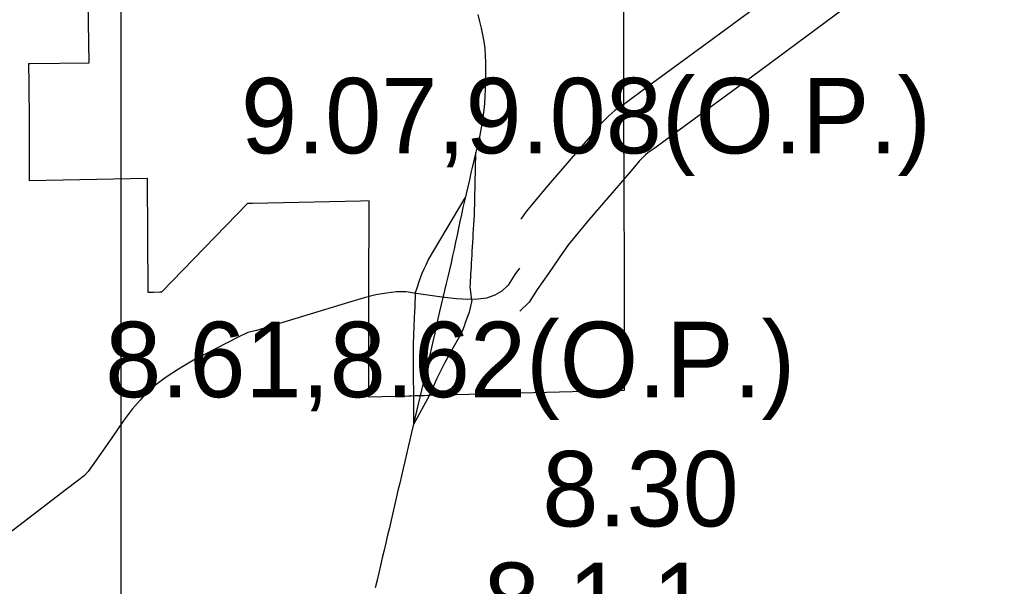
# Model space of a CAD drawing. Extents: x 1127717 to 1741049, y 2026793 to 2244711.
# Drawn here: x 1240828 to 1243581, y 2140586 to 2142172 of the extents above; entities that cross this region are included whole.
import ezdxf

# ---------------------------------------------------------------- set-up
doc = ezdxf.new("R2010")
doc.units = 0
for name, color, linetype in [('10', 7, 'Continuous'), ('30', 7, 'Continuous'), ('58', 7, 'Continuous'), ('6', 7, 'Continuous')]:
    doc.layers.add(name, color=color, linetype=linetype)

msp = doc.modelspace()

# ---------------------------------------------------------------- linework, layer by layer
at = {"layer": '10'}
for points in [[(1243898.9, 2143085.3), (1243769, 2142912), (1243734.4, 2142862.7), (1243709.9, 2142830.5), (1243698.6, 2142819.4), (1243674.7, 2142797.3), (1243491.4, 2142660.2), (1243211.8, 2142447.8), (1242963, 2142262.3), (1242790.6, 2142134.3), (1242584.6, 2141983.8), (1242522, 2141937.1), (1242493.2, 2141917.6), (1242476.6, 2141902.6), (1242450.7, 2141877.1), (1242424.4, 2141844.8), (1242306.6, 2141708.8), (1242245, 2141634.7), (1242230.2, 2141613.9)], [(1244018.9, 2142995.3), (1243890.4, 2142823.9), (1243855.5, 2142774.2), (1243822.8, 2142731.1), (1243802.2, 2142710.9), (1243771, 2142681.9), (1243581.7, 2142540.4), (1243302, 2142328), (1243052.6, 2142142), (1242879.6, 2142013.5), (1242673.7, 2141863.1), (1242608.9, 2141814.8), (1242585.9, 2141799.2), (1242579.4, 2141793.3), (1242561.8, 2141776), (1242539.3, 2141748.4), (1242421, 2141611.8), (1242363.9, 2141543.1), (1242339.2, 2141508.4), (1242308.1, 2141461.2), (1242275.8, 2141417), (1242253.4, 2141381.2), (1242227.4, 2141356.2)], [(1242109.8, 2142186), (1242114.7, 2142167.1), (1242119.1, 2142148.3), (1242123.1, 2142129.3), (1242126.5, 2142110.4), (1242129.4, 2142091.4), (1242131, 2142069), (1242131.7, 2142053.5), (1242131.4, 2142033.7)], [(1242131.4, 2142033.7), (1242131.6, 2142014.8), (1242131.3, 2141995.8), (1242130.7, 2141976.7), (1242129.8, 2141957.5), (1242128.4, 2141938), (1242126.5, 2141918.4), (1242124.1, 2141898.7), (1242121.2, 2141879), (1242117.8, 2141859.2), (1242113.9, 2141839.6), (1242109.6, 2141820.1), (1242104.9, 2141800.7), (1242100.1, 2141781.4), (1242095.4, 2141762.1), (1242090.9, 2141742.9), (1242086.5, 2141723.5), (1242082, 2141704.1), (1242077.4, 2141684.7), (1242072.8, 2141665.3), (1242068.3, 2141645.9), (1242064, 2141626.6), (1242059.9, 2141607.3), (1242055.9, 2141588), (1242052, 2141568.5), (1242048, 2141549.1)], [(1242093.7, 2141385.8), (1242089.2, 2141417.3), (1242089.1, 2141424.9), (1242089.5, 2141433), (1242089.9, 2141441.5), (1242090.4, 2141450.6), (1242090.9, 2141460), (1242091.4, 2141469.9), (1242092, 2141480.1), (1242092.7, 2141490.7), (1242093.3, 2141501.5), (1242094, 2141512.7), (1242094.7, 2141524.2), (1242095.4, 2141536), (1242096, 2141548), (1242096.7, 2141560.3), (1242097.5, 2141572.8), (1242098.3, 2141585.6), (1242099.2, 2141598.7), (1242100.9, 2141625.6), (1242104.8, 2141800.4)], [(1241959.6, 2141474.2), (1241965.4, 2141486.2), (1241971.6, 2141498.5), (1242074.8, 2141673.6)], [(1242048, 2141549.1), (1242043.8, 2141529.7), (1242039.6, 2141510.5), (1242035.2, 2141491.2), (1242030.8, 2141472), (1242026.3, 2141452.6), (1242021.7, 2141433.2), (1242017.1, 2141413.8), (1242012.5, 2141394.2), (1242007.8, 2141374.6), (1242003.3, 2141354.8), (1241998.7, 2141334.9), (1241994.1, 2141314.9), (1241989.5, 2141294.8), (1241984.8, 2141274.6), (1241980.2, 2141254.3), (1241975.5, 2141234), (1241970.8, 2141213.8), (1241966.2, 2141193.8), (1241961.7, 2141174), (1241957.1, 2141154.4), (1241952.5, 2141134.9), (1241947.9, 2141115.3), (1241943.2, 2141095.7), (1241938.6, 2141076), (1241934, 2141056.2), (1241929.4, 2141036.4), (1241924.9, 2141016.4), (1241920.3, 2140996.3), (1241915.6, 2140976.1), (1241910.7, 2140955.9), (1241905.9, 2140935.7), (1241901.1, 2140915.4), (1241896.3, 2140894.9), (1241891.5, 2140874.4), (1241886.7, 2140853.8), (1241881.9, 2140833.1), (1241877.1, 2140812.4), (1241872.3, 2140791.6), (1241867.5, 2140770.7), (1241862.6, 2140749.7), (1241857.7, 2140728.8), (1241852.8, 2140707.7), (1241847.9, 2140686.7), (1241842.9, 2140665.7), (1241838, 2140644.6), (1241833.1, 2140623.6), (1241828.2, 2140602.7), (1241823.3, 2140581.7)], [(1242226.6, 2141476.8), (1242213.7, 2141459.1), (1242194.8, 2141428.8), (1242177.4, 2141412.1), (1242157.8, 2141400.4), (1242134.6, 2141392.5), (1242110.8, 2141389.6), (1242081.8, 2141389.1), (1242050.8, 2141390.5), (1242009.2, 2141395.5), (1241937.9, 2141405.4), (1241909.3, 2141410.4), (1241882.8, 2141410), (1241855, 2141406.4), (1241825.2, 2141401.8), (1241792, 2141393.6), (1241748, 2141380.5), (1241490.6, 2141302.3), (1241466.4, 2141295.9), (1241439.4, 2141282.9), (1241314.3, 2141219.1), (1241272.7, 2141194), (1241235.2, 2141169.1), (1241202.1, 2141144.3), (1241183.2, 2141128.1), (1241165, 2141106.8), (1241142.9, 2141081.4), (1241118.1, 2141047.9), (1241085.8, 2141001.6), (1241030.7, 2140922.8), (1241019.7, 2140907.3), (1241008.7, 2140895.4), (1240988.7, 2140880.6), (1240958.6, 2140856.9), (1240283.3, 2140339.5)], [(1241935.1, 2141405.5), (1241941.3, 2141424.4), (1241945.4, 2141436.6), (1241947.1, 2141441.5), (1241950.6, 2141451.8), (1241954.7, 2141462.7), (1241959.6, 2141474.2)], [(1241935.1, 2141405.5), (1241934, 2141370.6), (1241932.6, 2141351.4), (1241932.1, 2141340), (1241931.7, 2141329.5), (1241931.2, 2141320.3), (1241930.8, 2141308.9), (1241930.3, 2141295.2), (1241929.9, 2141282.4), (1241929.4, 2141271.4), (1241929.1, 2141258.7), (1241930.1, 2141039.3)], [(1242093.7, 2141385.8), (1242085.6, 2141353.4), (1242082.2, 2141343), (1242078.9, 2141333.5), (1242075, 2141323.7), (1242071.5, 2141313.7), (1242066.9, 2141302.3), (1242061.3, 2141290.5), (1242054.8, 2141278.4), (1242047.8, 2141265.9)], [(1242047.8, 2141265.9), (1242040.6, 2141252.9), (1242033.2, 2141239.6), (1242025.6, 2141225.9), (1242017.9, 2141212), (1242010.1, 2141197.6), (1241995.2, 2141167.7), (1241974.9, 2141121.2), (1241930.1, 2141039.3)]]:
    msp.add_lwpolyline(points, dxfattribs=at)
at = {"layer": '30'}
msp.add_line((1241111.2, 2151684.2), (1241111.2, 2119636.1), dxfattribs=at)
at = {"layer": '6'}
for points in [[(1242517, 2142389.7), (1242517.6, 2142137.4), (1242517.6, 2142135.6), (1242517.6, 2142133.9), (1242517.7, 2142073.6), (1242517.7, 2142072.3), (1242517.7, 2142070.9), (1242518.2, 2141841.5), (1242518.2, 2141837.5), (1242518.2, 2141833.5), (1242518.4, 2141760.2), (1242519.2, 2141398.4), (1242519.2, 2141395.7), (1242519.2, 2141392.8), (1242519.5, 2141268.8), (1242519.8, 2141133.9), (1241976.8, 2141119.9), (1241973.8, 2141119.8), (1241970.9, 2141119.7), (1241970.8, 2141119.7), (1241961.2, 2141119.5), (1241961.2, 2141119.5), (1241958.3, 2141119.4), (1241955.5, 2141119.3), (1241953.2, 2141119.3), (1241951.5, 2141119.2), (1241944.6, 2141119), (1241943.3, 2141119), (1241940.4, 2141118.9), (1241937.6, 2141118.9), (1241934.7, 2141118.8), (1241923, 2141118.5), (1241920.3, 2141118.4), (1241917.5, 2141118.4), (1241804.9, 2141115.5)], [(1241804.9, 2141115.5), (1241805.1, 2141247.5), (1241805.4, 2141382.9), (1241805.4, 2141391.2), (1241805.4, 2141398.7), (1241805.9, 2141664.5), (1241782.1, 2141664), (1241479.3, 2141657.8), (1241465.8, 2141657.6), (1241224.9, 2141409.1), (1241220.5, 2141408.9), (1241202.7, 2141408.4), (1241200.1, 2141408.3), (1241197.5, 2141408.2), (1241187.9, 2141408), (1241185.4, 2141727), (1241184.5, 2141727), (1240855.8, 2141720.9), (1240855.8, 2141720.9), (1240855.6, 2141728.4), (1240855.5, 2141736), (1240855.5, 2141736), (1240855.9, 2141816), (1240856, 2141835.5), (1240855.7, 2141889), (1240855.2, 2141935), (1240855.1, 2141942.9), (1240854.5, 2141992.9), (1240853.8, 2142049.3), (1240857.1, 2142049.5), (1241022.2, 2142050.7), (1241017.5, 2142334.7)]]:
    msp.add_lwpolyline(points, dxfattribs=at)

# ---------------------------------------------------------------- texts
at = {"layer": '58'}
for s, p in [('9.07,9.08(O.P.)', (1241447.4, 2141797.7)), ('8.61,8.62(O.P.)', (1241067.3, 2141115.3)), ('8.30', (1242290.6, 2140753.5)), ('8.1 1', (1242126.9, 2140441.1))]:
    msp.add_text(s, height=211.2, dxfattribs=at).set_placement(p)

doc.saveas('drawing.dxf')
